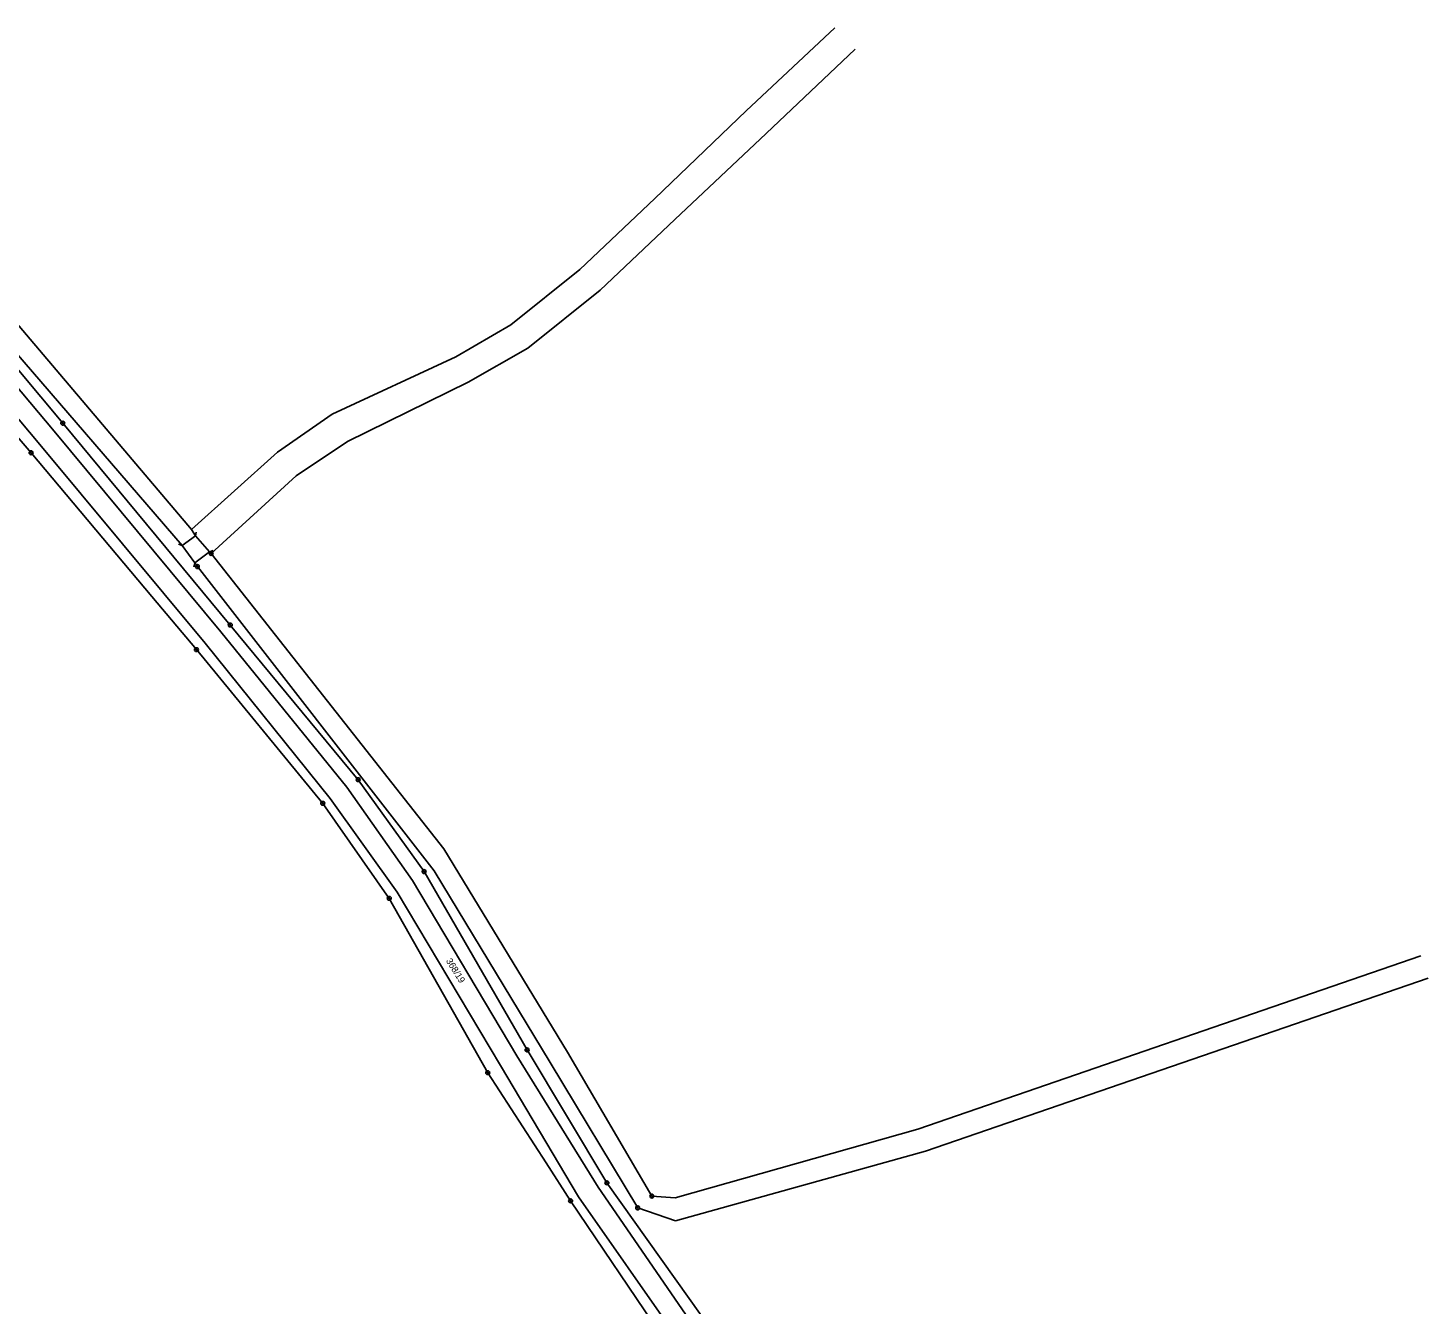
# Model space of a CAD drawing. Extents: x -762263 to -760336, y -1154405 to -1152076.
# Drawn here: x -760862.4 to -760503.1, y -1154077.7 to -1153750.2 of the extents above; entities that cross this region are included whole.
import ezdxf

# ---------------------------------------------------------------- set-up
doc = ezdxf.new("R2010")
doc.units = 0
for name, color, linetype in [('Vrstva 1', 7, 'Continuous'), ('Vrstva 13', 7, 'Continuous'), ('Vrstva 18', 7, 'Continuous'), ('Vrstva 24', 7, 'Continuous'), ('Vrstva 26', 7, 'Continuous'), ('Vrstva 4', 7, 'Continuous')]:
    doc.layers.add(name, color=color, linetype=linetype)

msp = doc.modelspace()

# ---------------------------------------------------------------- linework, layer by layer
at = {"layer": 'Vrstva 1'}
for p, q in [((-760678.05, -1153771.44), (-760655.33, -1153750.18)), ((-760650.09, -1153755.61), (-760672.99, -1153777.22)), ((-760701.54, -1153793.93), (-760678.05, -1153771.44)), ((-760672.99, -1153777.22), (-760696.35, -1153799.33)), ((-760720.81, -1153812.12), (-760701.54, -1153793.93)), ((-760820.46, -1153878.88), (-760886.7, -1153800.7)), ((-760696.35, -1153799.33), (-760715.58, -1153817.5)), ((-760891.66, -1153803.33), (-760822.84, -1153882.98)), ((-760738.46, -1153826.4), (-760720.81, -1153812.12)), ((-760715.58, -1153817.5), (-760734.1, -1153832.34)), ((-760853.45, -1153851.62), (-760877.14, -1153823.29)), ((-760752.57, -1153834.58), (-760738.46, -1153826.4)), ((-760734.1, -1153832.34), (-760749.4, -1153841.09)), ((-760784.36, -1153849.25), (-760752.57, -1153834.58)), ((-760749.4, -1153841.09), (-760780.43, -1153856.31)), ((-760798.32, -1153859.08), (-760784.36, -1153849.25)), ((-760810.47, -1153903.41), (-760853.45, -1153851.62)), ((-760780.43, -1153856.31), (-760793.52, -1153865.16)), ((-760820.46, -1153878.88), (-760798.32, -1153859.08)), ((-760793.52, -1153865.16), (-760815.38, -1153885.05)), ((-760820.46, -1153878.88), (-760819.41, -1153880.54)), ((-760822.84, -1153882.98), (-760819.58, -1153887.47)), ((-760819.41, -1153880.54), (-760815.78, -1153884.6)), ((-760819.58, -1153887.47), (-760818.91, -1153888.4)), ((-760815.78, -1153884.6), (-760815.38, -1153885.05)), ((-760755.69, -1153960.88), (-760815.38, -1153885.05)), ((-760758.12, -1153966.46), (-760818.91, -1153888.4)), ((-760810.47, -1153903.41), (-760777.66, -1153943.1)), ((-760777.66, -1153943.1), (-760760.74, -1153966.68)), ((-760723.92, -1154013.05), (-760755.69, -1153960.88)), ((-760728.34, -1154015.67), (-760758.12, -1153966.46)), ((-760734.3, -1154012.46), (-760760.74, -1153966.68)), ((-760505, -1153988.32), (-760634, -1154032.78)), ((-760632.04, -1154038.47), (-760503.12, -1153994.04)), ((-760713.83, -1154046.57), (-760734.3, -1154012.46)), ((-760702.3, -1154049.98), (-760723.92, -1154013.05)), ((-760705.92, -1154053), (-760728.34, -1154015.67)), ((-760634, -1154032.78), (-760696.31, -1154050.46)), ((-760632.04, -1154038.47), (-760696.19, -1154056.36)), ((-760674.37, -1154101.98), (-760713.83, -1154046.57)), ((-760696.31, -1154050.46), (-760702.3, -1154049.98)), ((-760696.19, -1154056.36), (-760705.92, -1154053))]:
    msp.add_line(p, q, dxfattribs=at)
at = {"layer": 'Vrstva 13'}
for p, q in [((-760867.22, -1153852.59), (-760861.59, -1153859.2)), ((-760861.59, -1153859.2), (-760830.59, -1153896.11)), ((-760830.59, -1153896.11), (-760819.16, -1153909.72)), ((-760819.16, -1153909.72), (-760786.73, -1153949.18)), ((-760786.73, -1153949.18), (-760769.67, -1153973.56)), ((-760769.67, -1153973.56), (-760744.4, -1154018.31)), ((-760744.4, -1154018.31), (-760729.42, -1154041.48)), ((-760729.42, -1154041.48), (-760723.14, -1154051.19)), ((-760723.14, -1154051.19), (-760699.65, -1154085.96))]:
    msp.add_line(p, q, dxfattribs=at)
at = {"layer": 'Vrstva 24'}
for centre, radius in [((-760853.45, -1153851.62), 0.5), ((-760853.45, -1153851.62), 0.1), ((-760861.59, -1153859.2), 0.5), ((-760861.59, -1153859.2), 0.1), ((-760815.38, -1153885.05), 0.5), ((-760815.38, -1153885.05), 0.1), ((-760818.91, -1153888.4), 0.5), ((-760818.91, -1153888.4), 0.1), ((-760810.47, -1153903.41), 0.5), ((-760810.47, -1153903.41), 0.1), ((-760819.16, -1153909.72), 0.5), ((-760819.16, -1153909.72), 0.1), ((-760777.66, -1153943.1), 0.5), ((-760777.66, -1153943.1), 0.1), ((-760786.73, -1153949.18), 0.5), ((-760786.73, -1153949.18), 0.1), ((-760760.74, -1153966.68), 0.5), ((-760760.74, -1153966.68), 0.1), ((-760769.67, -1153973.56), 0.5), ((-760769.67, -1153973.56), 0.1), ((-760734.3, -1154012.46), 0.5), ((-760734.3, -1154012.46), 0.1), ((-760744.4, -1154018.31), 0.5), ((-760744.4, -1154018.31), 0.1), ((-760713.83, -1154046.57), 0.5), ((-760713.83, -1154046.57), 0.1), ((-760723.14, -1154051.19), 0.5), ((-760723.14, -1154051.19), 0.1), ((-760705.92, -1154053), 0.5), ((-760702.3, -1154049.98), 0.5), ((-760702.3, -1154049.98), 0.1), ((-760705.92, -1154053), 0.1)]:
    msp.add_circle(centre, radius, dxfattribs=at)
at = {"layer": 'Vrstva 26'}
for p, q in [((-760819.41, -1153880.54), (-760819.261, -1153879.551)), ((-760822.84, -1153882.98), (-760823.789, -1153882.664)), ((-760819.58, -1153887.47), (-760819.809, -1153888.443)), ((-760815.78, -1153884.6), (-760814.821, -1153884.318))]:
    msp.add_line(p, q, dxfattribs=at)
at = {"layer": 'Vrstva 4'}
for p, q in [((-760879.63, -1153825.16), (-760855.67, -1153853.69)), ((-760859.32, -1153857.09), (-760883.7, -1153828.2)), ((-760855.67, -1153853.69), (-760812.91, -1153905.18)), ((-760816.89, -1153908.07), (-760859.32, -1153857.09)), ((-760822.84, -1153882.98), (-760819.41, -1153880.54)), ((-760819.58, -1153887.47), (-760815.78, -1153884.6)), ((-760812.91, -1153905.18), (-760780.53, -1153945.02)), ((-760784.8, -1153947.89), (-760816.89, -1153908.07)), ((-760780.53, -1153945.02), (-760763.71, -1153968.97)), ((-760767.63, -1153971.99), (-760784.8, -1153947.89)), ((-760736.9, -1154013.96), (-760763.71, -1153968.97)), ((-760767.63, -1153971.99), (-760741.14, -1154016.42)), ((-760741.14, -1154016.42), (-760721.09, -1154050.17)), ((-760716.07, -1154047.68), (-760736.9, -1154013.96)), ((-760677.15, -1154104.18), (-760716.07, -1154047.68)), ((-760721.09, -1154050.17), (-760681.11, -1154107.32))]:
    msp.add_line(p, q, dxfattribs=at)

# ---------------------------------------------------------------- texts
at = {"layer": 'Vrstva 18'}
msp.add_text('368/19', height=1.7, rotation=301.89146, dxfattribs=at).set_placement((-760755.195, -1153989.592))

doc.saveas('drawing.dxf')
